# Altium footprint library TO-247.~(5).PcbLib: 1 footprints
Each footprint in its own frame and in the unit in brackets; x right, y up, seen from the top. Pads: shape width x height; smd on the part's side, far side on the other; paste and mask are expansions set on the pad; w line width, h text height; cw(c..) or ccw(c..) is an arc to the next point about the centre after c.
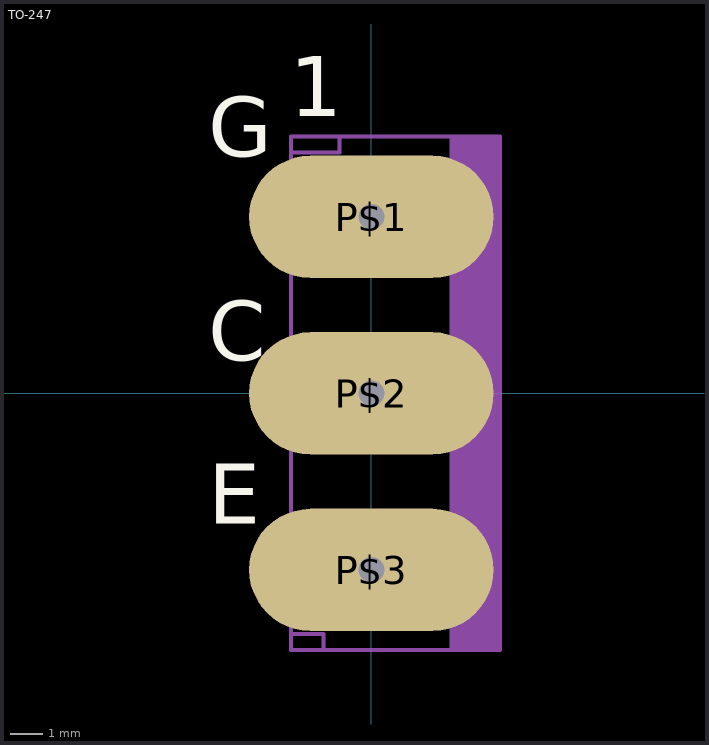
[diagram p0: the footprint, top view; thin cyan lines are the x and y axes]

## TO-247 [mm]
pads (3):
  oval 7.62x3.81 hole 0.8: P$1(0,5.5) P$2(0,0) P$3(0,-5.5)
Top Overlay:
  text "G" at -5.081,7.371 h1.88
  text "C" at -5.082,1.021 h1.88
  text "E" at -5.087,-4.066 h1.88
  text "1" at -2.54,8.641 h1.88
Mechanical 1:
  region: 2.502,8 3,8 3,-8.005 2.502,-8.005
  region: 2.502,8 4,8 4,-8.008 2.502,-8.008
  lines w0.127: -0.5,-5.5 -0.5,-5 ; -0.5,5.5 -0.5,5 ; 0,-1.5 -2.5,-1.5 ; -2.5,-7.5 -2.5,-8 -1.5,-8 ; -2.5,-7.5 -2.5,-1.5 ; -2.5,-7.5 -1.5,-7.5 -1.5,-8 ; -2.5,-1.5 -2.5,1.5 ; -2.5,-1.5 2.5,-1.5 ; -2.5,1.5 -2.5,7.5 ; -2.5,1.5 2.5,1.5 ; -2.5,7.5 -2.5,8 -1,8 ; -2.5,7.5 -1,7.5 -1,8 ; -1.5,-8 2.5,-8 ; -1,8 2.5,8 ; -0.5,-5 0.5,-5 0.5,-6 -0.5,-6 -0.5,-5 ; -0.5,5 -0.5,6 0.5,6 0.5,5 -0.5,5 ; 2.5,-8 2.5,-1.5 ; 2.5,-8 3,-8 ; 2.5,-1.5 2.5,1.5 ; 2.5,1.5 2.5,8 ; 2.5,8 3,8 ; 3,-8 3,8 ; 3,-8 4,-8 4,8 3,8 ; -0.5,-0.5 0.5,-0.5 0.5,0.5 -0.5,0.5 -0.5,-0.5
